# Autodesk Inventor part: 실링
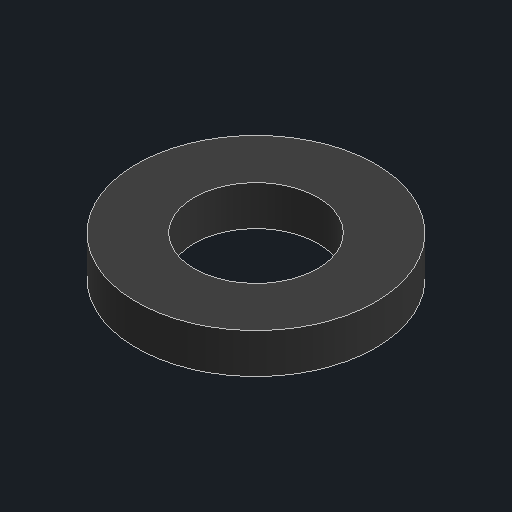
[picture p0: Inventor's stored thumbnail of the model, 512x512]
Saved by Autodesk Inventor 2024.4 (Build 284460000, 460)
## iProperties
Created: 2025-10
Part Number: 실링
Material: 고무
Document SubType Name: Modeling
Designer: user
Density: 0.93 g/cm^3
Appearance: 기본값
Author: jhkim
Sending System: Autodesk Inventor 2026
Preprocessor: ST-DEVELOPER v20.1
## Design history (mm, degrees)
feature "솔리드1"
node "솔리드2"
